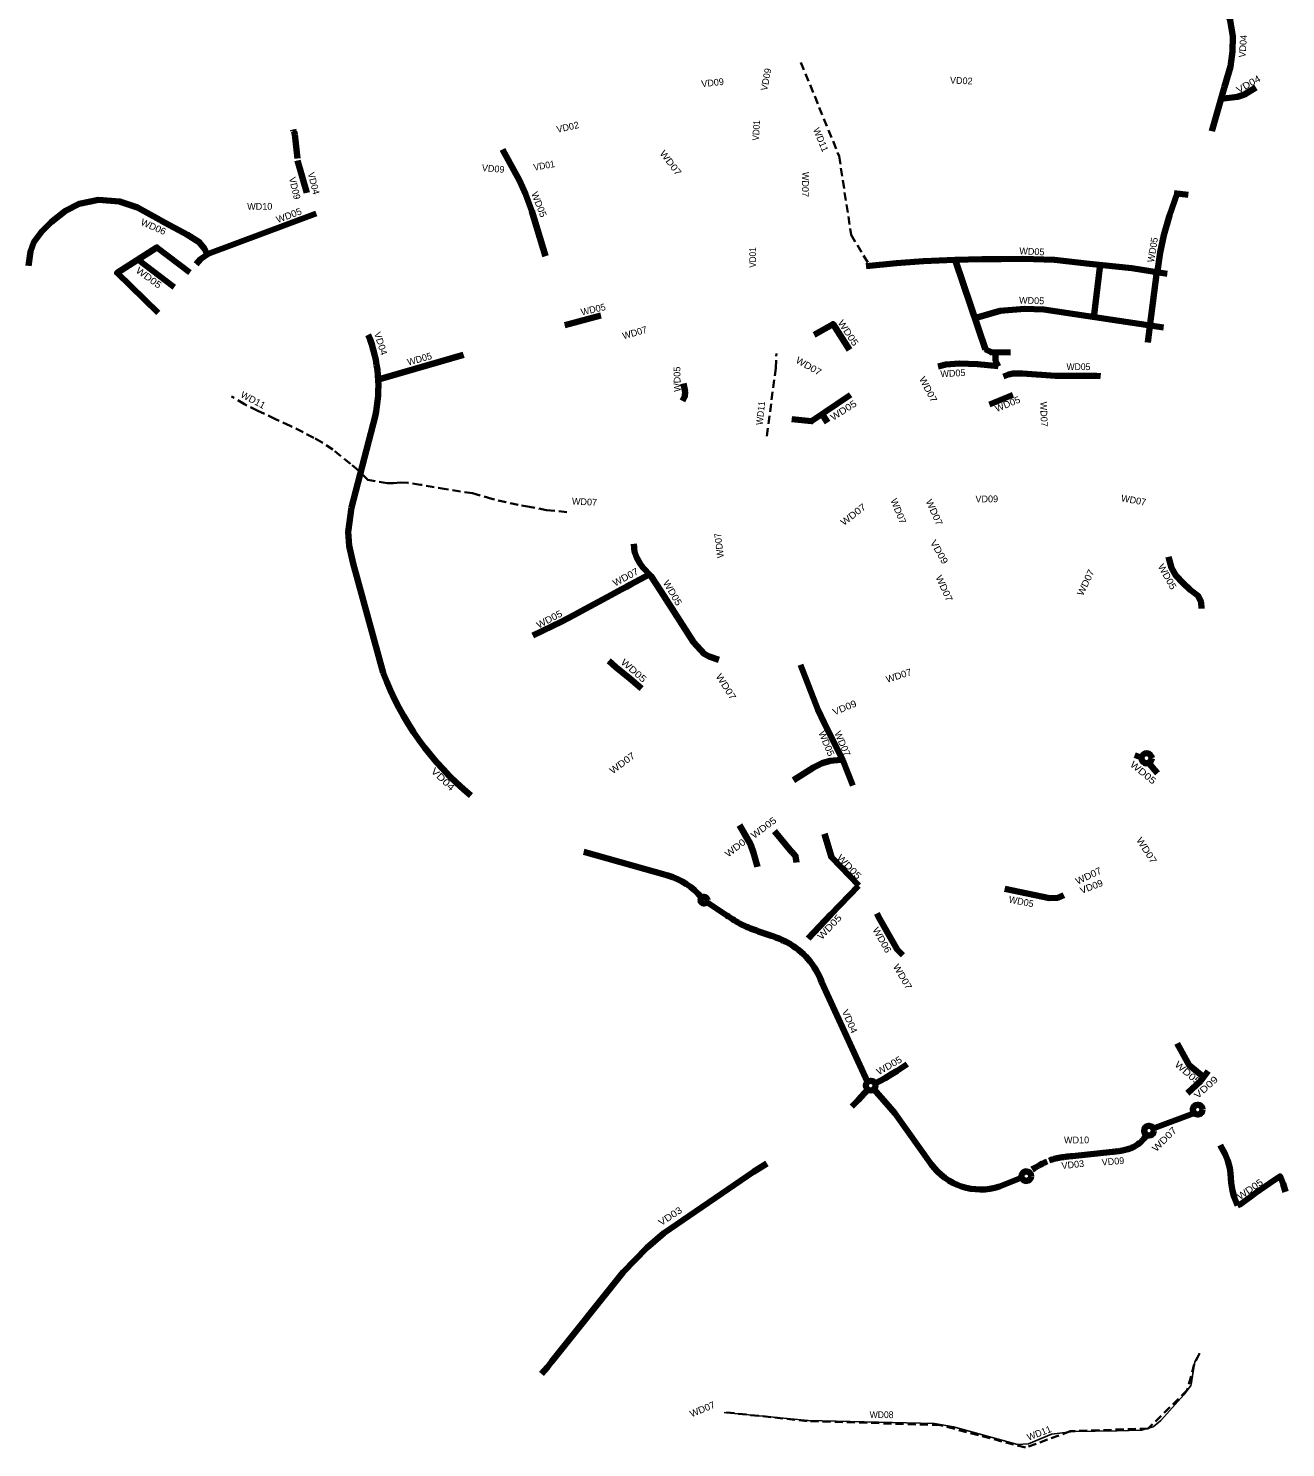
# Model space of a CAD drawing. Extents: x -650082 to -644047, y -1073232 to -1066669.
# Drawn here: x -650082 to -646363, y -1073058 to -1068858 of the extents above; entities that cross this region are included whole.
import ezdxf

# ---------------------------------------------------------------- set-up
doc = ezdxf.new("R2010")
doc.units = 0
doc.header["$LTSCALE"] = 8
doc.linetypes.add('MEDIUM_DASHED', pattern=[4.5, 3, -1.5])
for name, color, linetype in [('1', 7, 'Continuous'), ('10', 7, 'Continuous'), ('14', 7, 'Continuous'), ('15', 7, 'Continuous'), ('16', 7, 'Continuous'), ('2', 7, 'Continuous'), ('3', 7, 'Continuous'), ('4', 7, 'Continuous'), ('5', 7, 'Continuous'), ('6', 7, 'Continuous'), ('7', 7, 'Continuous'), ('9', 7, 'Continuous')]:
    doc.layers.add(name, color=color, linetype=linetype)
for name, color, linetype, lineweight in [('11', 7, 'Continuous', 106), ('12', 7, 'Continuous', 106), ('13', 7, 'MEDIUM_DASHED', 35), ('47', 7, 'Continuous', 106), ('48', 7, 'Continuous', 106), ('51', 7, 'Continuous', 106), ('52', 7, 'Continuous', 106), ('8', 7, 'Continuous', 25)]:
    doc.layers.add(name, color=color, linetype=linetype, lineweight=lineweight)

msp = doc.modelspace()

# ---------------------------------------------------------------- linework, layer by layer
at = {"layer": '11'}
for p, q in [((-649286.296, -1069243.402), (-649294.037, -1069172.192)), ((-649258.547, -1069344.39), (-649285.681, -1069249.06)), ((-649126.823, -1070275.677), (-649056.809, -1070006.786)), ((-648190.636, -1071365.392), (-648439.544, -1071295.299)), ((-647735.858, -1071680.067), (-647599.793, -1071975.634))]:
    msp.add_line(p, q, dxfattribs=at)
for points in [[(-646581.274, -1069162.086), (-646543.734, -1069031.454), (-646526.307, -1068970.81), (-646520.034, -1068926.895), (-646519.124, -1068882.525), (-646527.13, -1068833.717), (-646541.089, -1068803.463), (-646555.823, -1068777.863), (-646576.76, -1068753.039), (-646603.929, -1068734.295), (-646632.204, -1068718.474)], [(-646553.797, -1069066.473), (-646505.955, -1069060.333), (-646484.805, -1069053.474), (-646451.286, -1069033.122)], [(-649126.823, -1070275.677), (-649136.116, -1070347.82), (-649133.06, -1070389.586), (-649121.855, -1070441.538), (-649032.534, -1070765.134)], [(-648075.374, -1071443.872), (-648022.004, -1071479.581), (-648016.461, -1071483.285), (-648010.907, -1071486.974), (-648005.332, -1071490.629), (-647999.724, -1071494.234), (-647994.074, -1071497.773), (-647988.372, -1071501.227), (-647982.61, -1071504.58), (-647976.78, -1071507.812), (-647970.874, -1071510.906), (-647963.887, -1071513.957), (-647958.108, -1071516.621), (-647952.275, -1071519.164), (-647946.395, -1071521.599), (-647940.477, -1071523.938), (-647934.527, -1071526.195), (-647928.551, -1071528.382), (-647922.556, -1071530.515), (-647916.545, -1071532.605), (-647910.525, -1071534.668), (-647904.5, -1071536.717), (-647895.595, -1071539.745), (-647889.576, -1071541.81), (-647883.568, -1071543.908), (-647877.578, -1071546.054), (-647871.61, -1071548.265), (-647865.673, -1071550.555), (-647859.774, -1071552.942), (-647853.921, -1071555.438), (-647848.123, -1071558.061), (-647842.39, -1071560.823), (-647836.733, -1071563.738)]]:
    msp.add_lwpolyline(points, dxfattribs=at)
msp.add_circle((-648083.781, -1071438.172), 10.157, dxfattribs=at)
for centre, radius, start, end in [((-649390.897, -1069197.054), 100, 14.39558, 23.46117), ((-649452.625, -1069917.995), 405.652, 347.35635, 22.18649), ((-648232.695, -1070467.567), 853.398, 200.40686, 230.69896), ((-648244.965, -1071557.871), 200, 39.49461, 74.23772), ((-647937.958, -1071753.418), 215, 19.9479, 61.91292)]:
    msp.add_arc(centre, radius, start, end, dxfattribs=at)
at = {"layer": '12'}
for p, q in [((-646754.674, -1072114.023), (-646633.694, -1072068.165)), ((-646993.404, -1072195.535), (-646875.615, -1072182.532)), ((-647145.028, -1072259.442), (-647209.69, -1072285.315))]:
    msp.add_line(p, q, dxfattribs=at)
for points in [[(-647646.641, -1072049.031), (-647627.876, -1072030.328), (-647598.733, -1071998.754)], [(-647581.398, -1071997.866), (-647544.374, -1072039.387), (-647519.615, -1072068.332), (-647409.551, -1072222.875)], [(-647062.642, -1072208.565), (-647057.907, -1072206.959), (-647053.125, -1072205.5), (-647048.303, -1072204.179), (-647043.448, -1072202.984), (-647038.565, -1072201.905), (-647033.661, -1072200.931), (-647028.739, -1072200.051), (-647023.804, -1072199.253), (-647018.857, -1072198.525), (-647013.902, -1072197.856), (-647008.941, -1072197.235), (-647003.975, -1072196.649), (-646999.007, -1072196.086), (-646994.037, -1072195.536)], [(-646876.248, -1072183.165), (-646872.383, -1072182.737), (-646868.519, -1072182.3), (-646864.657, -1072181.844), (-646860.798, -1072181.36), (-646856.944, -1072180.839), (-646853.097, -1072180.272), (-646849.258, -1072179.649), (-646845.43, -1072178.963), (-646841.617, -1072178.202), (-646837.82, -1072177.36), (-646834.045, -1072176.427), (-646830.296, -1072175.394), (-646826.578, -1072174.254), (-646822.898, -1072172.998), (-646819.262, -1072171.619), (-646815.677, -1072170.111), (-646812.154, -1072168.466), (-646808.701, -1072166.678)], [(-647897.477, -1072217.517), (-647936.91, -1072242.12), (-648202.059, -1072423.781), (-648253.06, -1072467.272), (-648322.321, -1072539.514), (-648534.375, -1072804.118), (-648546.627, -1072820.111), (-648563.924, -1072839.863)], [(-647112.659, -1072235.417), (-647108.405, -1072232.79), (-647104.143, -1072230.176), (-647099.863, -1072227.591), (-647095.557, -1072225.05), (-647091.218, -1072222.565), (-647086.838, -1072220.154), (-647082.411, -1072217.83), (-647077.93, -1072215.611), (-647073.393, -1072213.512), (-647068.794, -1072211.549)]]:
    msp.add_lwpolyline(points, dxfattribs=at)
for centre in [(-647590.655, -1071986.8), (-646623.358, -1072058.099), (-646767.624, -1072120.384), (-647130.12, -1072255.012)]:
    msp.add_circle(centre, 14.428, dxfattribs=at)
for centre, radius, start, end in [((-646851.756, -1072087.012), 90, 298.5808, 324.78461), ((-647266.212, -1072116.452), 178.071, 215.23547, 288.50636)]:
    msp.add_arc(centre, radius, start, end, dxfattribs=at)
at = {"layer": '13'}
for points in [[(-647796.971, -1068958.769), (-647683.968, -1069236.597), (-647648.396, -1069468.745), (-647594.062, -1069560.317), (-647340.265, -1069541.717), (-647253.655, -1069810.08), (-647231.91, -1069823.971)], [(-647897.53, -1070064.61), (-647871.671, -1069864.156), (-647869.45, -1069820.63)], [(-648489.42, -1070289.79), (-648549.11, -1070283.64), (-648599.41, -1070274.03), (-648633.75, -1070268.38), (-648711.24, -1070250.44), (-648768.32, -1070233.86), (-648846.76, -1070222.17), (-648921.87, -1070208.67), (-648959.67, -1070203.09), (-648981.35, -1070202.4), (-649002.23, -1070203.94), (-649021.05, -1070203.56), (-649078.099, -1070194.501), (-649106.06, -1070166.8), (-649129.57, -1070146.73), (-649181.7, -1070104.45), (-649213.21, -1070083.53), (-649237.78, -1070069.79), (-649307.84, -1070034.18), (-649351.66, -1070014.26), (-649403.65, -1069989.85), (-649442.47, -1069970.36), (-649481, -1069947.32)], [(-646618.098, -1072779.957), (-646633.878, -1072812.319), (-646654.064, -1072888.773), (-646770.097, -1073001.842), (-647000.119, -1073009.906), (-647132.968, -1073058.363), (-647385.213, -1072991.734), (-647778.715, -1072979.619), (-648025.915, -1072953.371)]]:
    msp.add_lwpolyline(points, dxfattribs=at)
at = {"layer": '47'}
for p, q in [((-646692.985, -1069346.026), (-646651.217, -1069350.274)), ((-647339.967, -1069545.744), (-647251.088, -1069808.426)), ((-646912.03, -1069558.076), (-646930.389, -1069712.594)), ((-648494.915, -1069736.521), (-648388.804, -1069707.486)), ((-647207.164, -1069694.062), (-647282.295, -1069716.194)), ((-649043.757, -1069896.46), (-648795.401, -1069824.199)), ((-647170.402, -1069942.221), (-647239.362, -1069971.673)), ((-647718.115, -1070024.038), (-647733.777, -1069999.441)), ((-647672.743, -1071023.641), (-647643.873, -1071098.745)), ((-646808.839, -1071008.864), (-646795.926, -1071014.301)), ((-647824.318, -1071296.38), (-647875.239, -1071233.632)), ((-647708.122, -1071480.45), (-647626.882, -1071395.872)), ((-647708.122, -1071480.45), (-647775.697, -1071551.243))]:
    msp.add_line(p, q, dxfattribs=at)
for points in [[(-648552.408, -1069532.362), (-648592.697, -1069398.642), (-648611.424, -1069347.704), (-648629.402, -1069308.002), (-648679.548, -1069216.178)], [(-646742.322, -1069576.725), (-646734.087, -1069520.908), (-646723.107, -1069469.667), (-646706.636, -1069412.02), (-646684.285, -1069346.911)], [(-649586.177, -1069556.212), (-649573.053, -1069541.298), (-649550.047, -1069525.713), (-649230.786, -1069405.644)], [(-647603.51, -1069561.425), (-647514.414, -1069553.281), (-647434.342, -1069547.122), (-647341.331, -1069542.596), (-647262.07, -1069540.647), (-647204.248, -1069540.647), (-647140.134, -1069540.07), (-647047.049, -1069543.256), (-646943.2, -1069554.795), (-646817.923, -1069567.982), (-646714.075, -1069584.466)], [(-646744.044, -1069579.015), (-646764.641, -1069739.238), (-646770.927, -1069787.596)], [(-646724.352, -1069743.581), (-647078.839, -1069690.268), (-647135.789, -1069688.123), (-647207.164, -1069694.062)], [(-647757.476, -1069764.575), (-647701.982, -1069733.103), (-647653.087, -1069809.089)], [(-647390.821, -1069859.073), (-647368.021, -1069852.558), (-647328.004, -1069849.767), (-647274.492, -1069852.093), (-647213.899, -1069857.686)], [(-647251.088, -1069808.426), (-647232.613, -1069816.264), (-647177.241, -1069817.194)], [(-647213.795, -1069859.205), (-647220.933, -1069841.605), (-647221.408, -1069819.284)], [(-647197.567, -1069888.373), (-647182.853, -1069882.067), (-647168.927, -1069879.439), (-647141.6, -1069879.965), (-647044.065, -1069885.918), (-646922.882, -1069885.918), (-646911.17, -1069886.938)], [(-648147.091, -1069960.576), (-648140.266, -1069946.926), (-648139.508, -1069934.035), (-648144.058, -1069909.01)], [(-647650.097, -1069942.883), (-647765.549, -1070020.915), (-647823.598, -1070014.961)], [(-648290.966, -1070383.374), (-648288.845, -1070406.899), (-648282.079, -1070425.044), (-648273.16, -1070440.728), (-648264.17, -1070453.236), (-648241.202, -1070478.118), (-648211.195, -1070523.918)], [(-646709.343, -1070422.319), (-646700.372, -1070454.216), (-646687.863, -1070477.44), (-646666.258, -1070500.316), (-646645.289, -1070519.379), (-646621.777, -1070537.807), (-646613.517, -1070556.235), (-646612.246, -1070574.663)], [(-648589.664, -1070655.082), (-648504.268, -1070613.585), (-648469.046, -1070594.986), (-648434.122, -1070576.22), (-648370.201, -1070541.371), (-648326.641, -1070517.498), (-648313.175, -1070510.435), (-648300.652, -1070503.633), (-648244.358, -1070473.301)], [(-648039.532, -1070726.638), (-648068.169, -1070717.378), (-648082.709, -1070709.44), (-648115.092, -1070674.163), (-648211.195, -1070523.918)], [(-648268.369, -1070811.262), (-648303.087, -1070781.942), (-648344.753, -1070748.129), (-648364.772, -1070729.983)], [(-647798.303, -1070741.695), (-647747.4, -1070874.36), (-647727.829, -1070913.158), (-647672.743, -1071023.641)], [(-647677.55, -1071022.921), (-647710.774, -1071025.971), (-647733.735, -1071032.504), (-647759.543, -1071045.17), (-647818.707, -1071082.607)], [(-646741.751, -1071062.202), (-646751.573, -1071052.898), (-646766.082, -1071034.526)], [(-647925.368, -1071339.891), (-647936.852, -1071298.253), (-647946.561, -1071272.093), (-647978.731, -1071216.254)], [(-647727.338, -1071242.207), (-647706.62, -1071310.667), (-647625.686, -1071394.72)], [(-647810.393, -1071327.127), (-647812.572, -1071307.894), (-647823.337, -1071295.659)], [(-647193.49, -1071404.445), (-647061.509, -1071431.827), (-647037.352, -1071430.861), (-647019.146, -1071423.327)], [(-646684.409, -1071862), (-646648.676, -1071926.01), (-646609.296, -1071959.529)], [(-647577.687, -1071980.477), (-647548.027, -1071965.02), (-647528.6, -1071953.175), (-647512.49, -1071943.224), (-647482.989, -1071923.852)], [(-646592.707, -1071943.76), (-646614.335, -1071972.381), (-646653.429, -1072008.981)], [(-646556.924, -1072163.008), (-646541.975, -1072190.142), (-646534.08, -1072209.348), (-646528.451, -1072231.169), (-646526.022, -1072245.895), (-646524.078, -1072274.419), (-646520.515, -1072298.567), (-646515.575, -1072317.043), (-646505.446, -1072341.949)], [(-646505.446, -1072341.949), (-646496.463, -1072338.193), (-646468.402, -1072317.124), (-646451.071, -1072304.158), (-646409.932, -1072275.634), (-646379.686, -1072255.456), (-646370.251, -1072277.255), (-646363.282, -1072301.269)]]:
    msp.add_lwpolyline(points, dxfattribs=at)
msp.add_circle((-646774.452, -1071018.284), 15.055, dxfattribs=at)
at = {"layer": '48'}
msp.add_line((-649650.964, -1069624.206), (-649758.457, -1069542.558), dxfattribs=at)
msp.add_lwpolyline([(-649698.475, -1069700.198), (-649819.737, -1069581.875), (-649701.821, -1069506.22), (-649604.8, -1069580.077)], dxfattribs=at)
at = {"layer": '51'}
for points in [[(-649690.862, -1069426.602), (-649693.075, -1069424.839), (-649759.229, -1069388.516), (-649812.457, -1069370.063), (-649874.912, -1069365.805), (-649931.689, -1069377.161), (-649972.852, -1069398.452), (-650014.541, -1069431.96), (-650043.673, -1069460), (-650065.774, -1069491.142), (-650076.339, -1069518.627), (-650082.165, -1069560.934)], [(-647572.568, -1071477.763), (-647563.965, -1071494.251), (-647512.351, -1071583.86), (-647495.989, -1071600.795)]]:
    msp.add_lwpolyline(points, dxfattribs=at)
at = {"layer": '52'}
msp.add_lwpolyline([(-649553.361, -1069527.958), (-649560.675, -1069511.85), (-649576.968, -1069490.717), (-649611.664, -1069468.981), (-649690.862, -1069426.602)], dxfattribs=at)
at = {"layer": '8'}
for points in [[(-646641.615, -1072861.847), (-646642.788, -1072871.592), (-646636.323, -1072833.305), (-646631.944, -1072804.277), (-646618.055, -1072778.52)], [(-648023.648, -1072953.961), (-647775.451, -1072978.577), (-647402.33, -1072986.644), (-647345.858, -1072996.728), (-647156.272, -1073049.167), (-647124.002, -1073047.15), (-647055.429, -1073018.914), (-646990.889, -1073010.846), (-646861.81, -1073008.83), (-646789.202, -1073006.813), (-646754.915, -1072996.728), (-646732.73, -1072978.577), (-646664.156, -1072901.935), (-646642.762, -1072873.366)]]:
    msp.add_lwpolyline(points, dxfattribs=at)

# ---------------------------------------------------------------- texts
at = {"layer": '1'}
for rotation, width, p in [(86.772, 0.9, (-647921.103, -1069190.627)), (9.97, 0.95, (-648586.178, -1069279.341)), (90.083, 0.9, (-647929.691, -1069566.304))]:
    msp.add_text('VD01', height=20, rotation=rotation, dxfattribs=dict(at, width=width)).set_placement(p)
at = {"layer": '10'}
for p in [(-649434.865, -1069395.02), (-647018.705, -1072158.017)]:
    msp.add_text('WD10', height=20, rotation=0.318, dxfattribs=at).set_placement(p)
at = {"layer": '14'}
for rotation, p in [(292.311, (-647761.508, -1069157.121)), (20.83, (-647123.491, -1073037.925))]:
    msp.add_text('WD11', height=20, rotation=rotation, dxfattribs=at).set_placement(p)
for rotation, width, p in [(332.078, 1.05, (-649456.64, -1069948.265)), (83.81, 0.95, (-647910.311, -1070032.951))]:
    msp.add_text('WD11', height=20, rotation=rotation, dxfattribs=dict(at, width=width)).set_placement(p)
at = {"layer": '15', "width": 1.15}
msp.add_text('WD05', height=20, rotation=323.794, dxfattribs=at).set_placement((-649766.25, -1069578.722))
at = {"layer": '16', "width": 1.05}
msp.add_text('WD06', height=20, rotation=336.373, dxfattribs=at).set_placement((-649751.99, -1069438.856))
at = {"layer": '2'}
for rotation, p in [(357.375, (-647356.457, -1069021.082)), (12.542, (-648517.473, -1069167.221))]:
    msp.add_text('VD02', height=20, rotation=rotation, dxfattribs=at).set_placement(p)
at = {"layer": '3'}
msp.add_text('VD03', height=20, rotation=6.009, dxfattribs=at).set_placement((-647025.037, -1072234.169))
at = {"layer": '3', "width": 1.15}
msp.add_text('VD03', height=20, rotation=33.391, dxfattribs=at).set_placement((-648210.42, -1072403.064))
at = {"layer": '4'}
for rotation, p in [(85.893, (-646482.108, -1068944.939)), (284.235, (-649256.065, -1069286.662))]:
    msp.add_text('VD04', height=20, rotation=rotation, dxfattribs=at).set_placement(p)
for rotation, width, p in [(29.411, 1.15, (-646502.014, -1069050.708)), (287.6, 1.05, (-649060.021, -1069760.208)), (316.159, 1.25, (-648893.138, -1071058.344)), (293.494, 1.1, (-647676.428, -1071767.021))]:
    msp.add_text('VD04', height=20, rotation=rotation, dxfattribs=dict(at, width=width)).set_placement(p)
at = {"layer": '5'}
for rotation, width, p in [(291.57, 1.05, (-648595.322, -1069346.682)), (20.413, 1.05, (-649344.656, -1069434.505)), (303.586, 1.15, (-647689.055, -1069729.375)), (359.771, 0.95, (-647011.407, -1069869.205)), (32.763, 1.15, (-647701.559, -1070019.86)), (22.562, 1.05, (-647217.993, -1069994.051)), (299.409, 1.1, (-646742.052, -1070450.235)), (300.371, 1.1, (-648205.967, -1070498.405)), (27.93, 1.1, (-648572.628, -1070634.584)), (318.812, 1.2, (-648331.556, -1070736.821)), (292.87, 1.05, (-647745.74, -1070942.497)), (320.604, 1.2, (-646825.309, -1071040.045)), (36.91, 1.15, (-647935.396, -1071257.441)), (313.863, 1.2, (-647692.262, -1071314.022)), (46.414, 1.2, (-647735.69, -1071556.53)), (29.944, 1.1, (-647566.364, -1071956.55)), (319.129, 1.2, (-646693.266, -1071927.68)), (34.487, 1.15, (-646498.118, -1072326.083))]:
    msp.add_text('WD05', height=20, rotation=rotation, dxfattribs=dict(at, width=width)).set_placement(p)
for rotation, p in [(357.197, (-647151.356, -1069526.302)), (80.615, (-646752.852, -1069551.846)), (12.814, (-648445.492, -1069707.786)), (358.177, (-647151.994, -1069672.198)), (15.559, (-648958.337, -1069856.049)), (90.808, (-648152.699, -1069933.435)), (2.857, (-647383.984, -1069890.409)), (348.607, (-647183.65, -1071444.769))]:
    msp.add_text('WD05', height=20, rotation=rotation, dxfattribs=at).set_placement(p)
at = {"layer": '6', "width": 1.1}
msp.add_text('WD06', height=20, rotation=299.586, dxfattribs=at).set_placement((-647586.001, -1071525.44))
at = {"layer": '7'}
for rotation, width, p in [(307.201, 1.15, (-648216.084, -1069228.211)), (330.302, 1.1, (-647814.4, -1069846.044)), (297.667, 1.1, (-647448.246, -1069895.109)), (37.889, 1.15, (-647669.893, -1070330.992)), (292.116, 1.05, (-647532.629, -1070254.406)), (294.454, 1.1, (-647428.465, -1070257.434)), (28.414, 1.1, (-648346.892, -1070510.452)), (294.454, 1.1, (-647399.207, -1070482.213)), (64.535, 1.1, (-646963.014, -1070539.33)), (302.302, 1.15, (-648049.847, -1070775.71)), (17.803, 1.05, (-647541.835, -1070795.135)), (293.26, 1.05, (-647698.608, -1070943.099)), (36.212, 1.15, (-648354.157, -1071065.604)), (37.876, 1.15, (-648012.3, -1071312.413)), (302.643, 1.15, (-646805.959, -1071260.156)), (25.46, 1.1, (-646978.911, -1071392.769)), (299.885, 1.1, (-647525.38, -1071634.155)), (45.026, 1.2, (-646746.182, -1072184.521)), (22.432, 1.05, (-648120.604, -1072968.926))]:
    msp.add_text('WD07', height=20, rotation=rotation, dxfattribs=dict(at, width=width)).set_placement(p)
for rotation, p in [(269.034, (-647793.034, -1069282.646)), (16.02, (-648321.58, -1069778.479)), (272.013, (-647089.498, -1069963.268)), (357.034, (-648474.765, -1070267.044)), (349.845, (-646850.986, -1070257.62)), (97.026, (-648024.784, -1070424.219))]:
    msp.add_text('WD07', height=20, rotation=rotation, dxfattribs=at).set_placement(p)
at = {"layer": '8', "width": 0.95}
msp.add_text('WD08', height=20, rotation=359.822, dxfattribs=at).set_placement((-647593.734, -1072970.888))
at = {"layer": '9'}
for rotation, p in [(6.253, (-648090.523, -1069032.33)), (78.961, (-647896.883, -1069044.007)), (355.112, (-648741.445, -1069280.24)), (283.42, (-649311.686, -1069300.906)), (0.216, (-647280.667, -1070260.641)), (4.69, (-646906.544, -1072223.962))]:
    msp.add_text('VD09', height=20, rotation=rotation, dxfattribs=at).set_placement(p)
for rotation, width, p in [(299.658, 1.15, (-647415.603, -1070379.066)), (22.494, 1.1, (-647698.244, -1070891.729)), (20.79, 1.05, (-646967.13, -1071419.926)), (41.768, 1.25, (-646623.484, -1072027.315))]:
    msp.add_text('VD09', height=20, rotation=rotation, dxfattribs=dict(at, width=width)).set_placement(p)

doc.saveas('drawing.dxf')
